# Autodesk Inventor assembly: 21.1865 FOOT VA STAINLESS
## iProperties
Created: 2007-11
Part Number: 21.1865 FOOT VA STAINLESS
Document SubType Name: Assembly
Designer: Andy Moles
Mass: 230.795 g
Surface Area: 78.7834 cm^2
Volume: 28.568 cm^3
Density: 8.0788 g/cm^3
Author: Andy Moles
